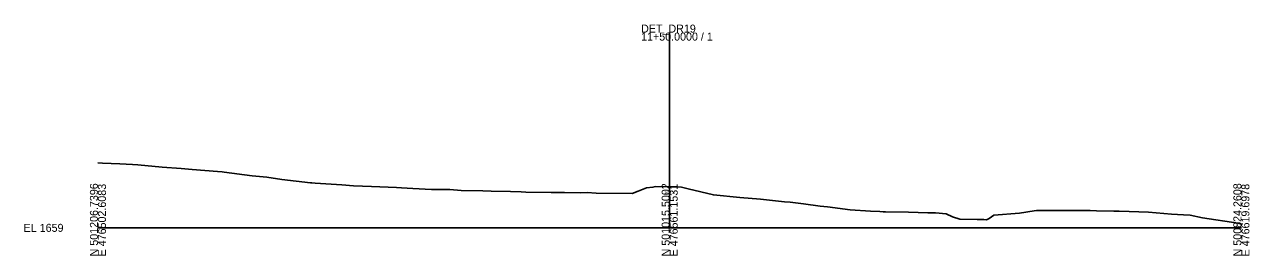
# Model space of a CAD drawing. Extents: x -26 to 403, y -10 to 3059.
# Drawn here: x -25.7 to 402.8, y 2490.3 to 2571.2 of the extents above; entities that cross this region are included whole.
import ezdxf

# ---------------------------------------------------------------- set-up
doc = ezdxf.new("R2010")
doc.units = 0
for name, color, linetype in [('Exist Cross Section Cell', 7, 'Continuous'), ('Exist XS Center Line Elevation Label', 7, 'Continuous'), ('Exist XS Ground Line', 7, 'Continuous')]:
    doc.layers.add(name, color=color, linetype=linetype)

msp = doc.modelspace()

# ---------------------------------------------------------------- linework, layer by layer
at = {"layer": 'Exist Cross Section Cell'}
for p, q in [((200, 2500), (200, 2568.36)), ((0, 2500), (200, 2500)), ((200, 2500), (400, 2500))]:
    msp.add_line(p, q, dxfattribs=at)
at = {"layer": 'Exist XS Ground Line'}
msp.add_lwpolyline([(0, 2522.79), (1.6, 2522.68), (7.64, 2522.4), (12.06, 2522.2), (14.01, 2522.02), (22.52, 2521.3), (29.09, 2520.76), (32.98, 2520.48), (41.81, 2519.7), (43.44, 2519.56), (44.16, 2519.47), (53.9, 2518.2), (59.08, 2517.78), (64.36, 2516.92), (74.31, 2515.78), (74.82, 2515.74), (75.98, 2515.65), (85.28, 2515.05), (89.39, 2514.74), (95.74, 2514.48), (104.46, 2514.11), (106.2, 2514.04), (110.14, 2513.8), (116.66, 2513.45), (123.14, 2513.37), (127.12, 2513.12), (134.61, 2512.94), (137.58, 2512.88), (144.31, 2512.67), (148.04, 2512.56), (149.69, 2512.52), (158.5, 2512.4), (163.19, 2512.42), (168.96, 2512.29), (171.19, 2512.34), (174.28, 2512.15), (186.88, 2511.98), (188.97, 2512.8), (191.84, 2513.95), (194.17, 2514.24), (195.05, 2514.43), (200, 2514.35), (202.18, 2514.32), (204.14, 2514.24), (206.53, 2513.6), (215.3, 2511.55), (224.54, 2510.64), (231.72, 2510), (240.14, 2509.15), (242.18, 2508.96), (246.82, 2508.38), (252.64, 2507.6), (255.22, 2507.39), (263.1, 2506.34), (270.29, 2505.81), (273.56, 2505.72), (274.63, 2505.63), (275.5, 2505.59), (283.52, 2505.45), (290.28, 2505.23), (293, 2505.23), (296.76, 2504.9), (298.91, 2503.91), (301.47, 2503.09), (307.56, 2502.94), (309.95, 2502.9), (310.85, 2502.83), (311.8, 2503.32), (313.44, 2504.41), (322.41, 2505.14), (327.48, 2505.91), (328.27, 2506.03), (335.37, 2506.08), (345.68, 2506.04), (346.66, 2506.08), (347.08, 2506.08), (349.32, 2506.01), (355.39, 2505.84), (357.25, 2505.81), (360.74, 2505.68), (367.55, 2505.51), (375.57, 2504.82), (379.7, 2504.53), (382.08, 2504.39), (386.41, 2503.49), (398.9, 2501.65), (400, 2501.23)], dxfattribs=at)

# ---------------------------------------------------------------- texts
at = {"layer": 'Exist Cross Section Cell'}
for s, p in [('DET_DR19', (190, 2568.36)), ('11+50.0000 / 1', (190, 2565.56)), ('EL 1659', (-26, 2498.6))]:
    msp.add_text(s, height=2.8, dxfattribs=at).set_placement(p)
for s, p in [('N 501206.7396', (0, 2490)), ('E 476502.6083', (2.8, 2490)), ('N 501015.5002', (200, 2490)), ('E 476561.1531', (202.8, 2490)), ('N 500824.2608', (400, 2490)), ('E 476619.6978', (402.8, 2490))]:
    msp.add_text(s, height=2.8, rotation=90, dxfattribs=at).set_placement(p)
at = {"layer": 'Exist XS Center Line Elevation Label'}
msp.add_text('1673.35', height=0.75, dxfattribs=at).set_placement((198.21, 2511.98))

doc.saveas('drawing.dxf')
